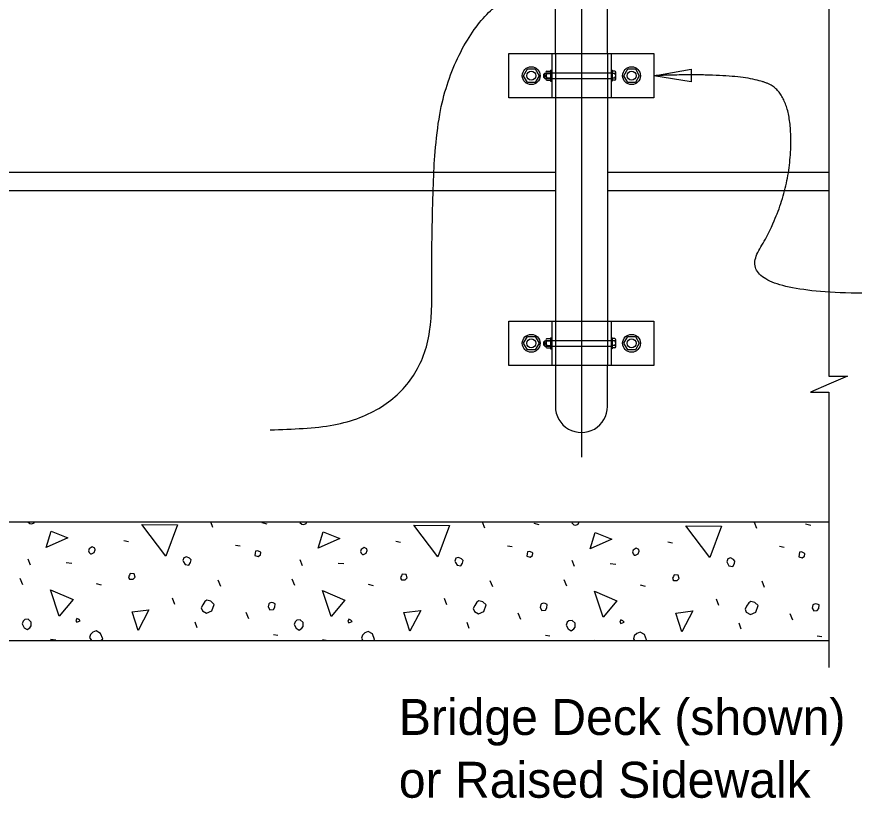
# Model space of a CAD drawing. Extents: x 0 to 41.1, y 0 to 26.4.
# Drawn here: x 19.043 to 23.735, y 12.919 to 17.3 of the extents above; entities that cross this region are included whole.
import ezdxf

# ---------------------------------------------------------------- set-up
doc = ezdxf.new("R2010")
doc.units = 0
for name, color, linetype in [('CL_Major', 7, 'Continuous'), ('Dimension', 7, 'Continuous'), ('Miscellaneous', 7, 'Continuous'), ('SteelMisc', 7, 'Continuous'), ('SteelMisc_h', 7, 'Continuous'), ('SupstrConc', 7, 'Continuous')]:
    doc.layers.add(name, color=color, linetype=linetype)

msp = doc.modelspace()

# ---------------------------------------------------------------- linework, layer by layer
at = {"layer": 'CL_Major'}
msp.add_line((22.2062, 25.6784), (22.2062, 14.8312), dxfattribs=at)
at = {"layer": 'Dimension'}
for points in [[(23.5932, 20.1983), (23.5932, 19.1806), (23.6966, 19.1806), (23.5932, 19.1356), (23.4899, 19.0906), (23.5932, 19.0906), (23.5932, 16.8862)], [(23.5932, 17.1362), (23.5932, 15.2854), (23.6966, 15.2854), (23.5932, 15.2404), (23.4899, 15.1954), (23.5932, 15.1954), (23.5932, 13.6529)]]:
    msp.add_lwpolyline(points, dxfattribs=at)
msp.add_lwpolyline([(22.8207, 16.9356), (22.6122, 16.9694), (22.8202, 17.0062)], close=True, dxfattribs=at)
for points in [[(20.4632, 14.9843), (21.3717, 14.9643), (21.3652, 16.4454), (21.4405, 16.9433), (21.6515, 17.3204), (21.8903, 17.4554), (21.9647, 17.4872), (22.0043, 17.5089), (21.982, 17.3708), (21.7151, 17.4193)], [(23.9932, 15.7529), (23.0399, 15.7236), (23.3618, 16.2556), (23.3935, 16.8155), (23.1813, 16.9916), (22.6122, 16.9694)]]:
    msp.add_open_spline(points, degree=2, dxfattribs=at)
at = {"layer": 'Miscellaneous'}
for p, q in [((21.9986, 16.9625), (21.9986, 16.9746)), ((22.0044, 16.9625), (22.0044, 16.9746)), ((21.9986, 15.4625), (21.9986, 15.4746)), ((22.0044, 15.4625), (22.0044, 15.4746)), ((20.141, 14.4376), (20.1292, 14.4695)), ((20.415, 14.4641), (20.4432, 14.4571)), ((21.6648, 14.4341), (21.6524, 14.4677)), ((21.9388, 14.4606), (21.9671, 14.4535)), ((23.1886, 14.4306), (23.1762, 14.4641)), ((23.4626, 14.4571), (23.4909, 14.45)), ((19.6424, 14.3634), (19.669, 14.3581)), ((21.1663, 14.3599), (21.1928, 14.3545)), ((20.2682, 14.3386), (20.2947, 14.3333)), ((21.792, 14.3351), (21.8186, 14.3298)), ((22.6901, 14.3563), (22.7166, 14.351)), ((23.3159, 14.3316), (23.3424, 14.3263)), ((19.1192, 14.2255), (19.1068, 14.2591)), ((19.3189, 14.2414), (19.3508, 14.2379)), ((20.643, 14.222), (20.6306, 14.2556)), ((20.8428, 14.2379), (20.8746, 14.2343)), ((22.1668, 14.2184), (22.1544, 14.252)), ((22.3666, 14.2343), (22.3984, 14.2308)), ((19.0768, 14.1159), (19.0626, 14.1513)), ((20.1851, 14.1071), (20.171, 14.1424)), ((20.6006, 14.1124), (20.5864, 14.1477)), ((21.709, 14.1035), (21.6948, 14.1389)), ((22.1244, 14.1088), (22.1102, 14.1442)), ((23.2328, 14.1), (23.2186, 14.1353)), ((19.4869, 14.123), (19.5152, 14.1159)), ((21.0107, 14.1194), (21.039, 14.1124)), ((22.5345, 14.1159), (22.5628, 14.1088)), ((19.9288, 14.0063), (19.9147, 14.0417)), ((21.4526, 14.0028), (21.4385, 14.0381)), ((22.9765, 13.9992), (22.9623, 14.0346)), ((20.3425, 13.925), (20.3283, 13.9603)), ((21.8663, 13.9214), (21.8522, 13.9568)), ((23.3901, 13.9179), (23.376, 13.9533)), ((20.0543, 13.8737), (20.042, 13.9073)), ((21.5781, 13.8702), (21.5658, 13.9038)), ((23.102, 13.8666), (23.0896, 13.9002)), ((19.2323, 13.8118), (19.2624, 13.8065)), ((20.4804, 13.8366), (20.5051, 13.8331)), ((20.7561, 13.8083), (20.7862, 13.803)), ((22.0042, 13.8331), (22.0289, 13.8295)), ((22.28, 13.8048), (22.2912, 13.8028)), ((23.528, 13.8295), (23.5527, 13.826))]:
    msp.add_line(p, q, dxfattribs=at)
for points in [[(19.105, 14.4695), (19.1156, 14.4588)], [(19.1156, 14.4588), (19.128, 14.4571), (19.1404, 14.4624), (19.1428, 14.4695)], [(19.8776, 14.2768), (19.7432, 14.4535), (19.943, 14.4518), (19.8776, 14.2768)], [(20.63, 14.4695), (20.6289, 14.4659), (20.6395, 14.4553)], [(20.6395, 14.4553), (20.6518, 14.4535), (20.6642, 14.4588), (20.6677, 14.4695)], [(22.155, 14.4695), (22.1527, 14.4624), (22.1633, 14.4518)], [(22.1633, 14.4518), (22.1757, 14.45), (22.188, 14.4553), (22.1916, 14.4659), (22.1894, 14.4695)], [(19.2076, 14.3245), (19.2359, 14.4164), (19.3295, 14.3793), (19.2076, 14.3245)], [(20.7314, 14.321), (20.7597, 14.4129), (20.8534, 14.3758), (20.7314, 14.321)], [(21.4014, 14.2732), (21.267, 14.45), (21.4668, 14.4482), (21.4014, 14.2732)], [(22.2552, 14.3174), (22.2835, 14.4093), (22.3772, 14.3722), (22.2552, 14.3174)], [(22.9252, 14.2697), (22.7908, 14.4465), (22.9906, 14.4447), (22.9252, 14.2697)], [(19.4551, 14.2891), (19.4621, 14.2891), (19.4763, 14.2962), (19.4816, 14.3121), (19.4798, 14.321), (19.4657, 14.328), (19.448, 14.3174), (19.4445, 14.3068), (19.448, 14.2962), (19.4551, 14.2891)], [(20.9789, 14.2856), (20.9859, 14.2856), (21.0001, 14.2927), (21.0054, 14.3086), (21.0036, 14.3174), (20.9895, 14.3245), (20.9718, 14.3139), (20.9683, 14.3033), (20.9718, 14.2927), (20.9789, 14.2856)], [(22.5027, 14.2821), (22.5098, 14.2821), (22.5239, 14.2891), (22.5292, 14.305), (22.5274, 14.3139), (22.5133, 14.321), (22.4956, 14.3104), (22.4921, 14.2997), (22.4956, 14.2891), (22.5027, 14.2821)], [(19.9766, 14.2449), (19.9854, 14.229), (20.0066, 14.2255), (20.0154, 14.2414), (20.019, 14.2556), (20.0101, 14.2644), (19.9942, 14.2732), (19.9783, 14.2679), (19.973, 14.252), (19.9766, 14.2449)], [(20.3761, 14.2803), (20.3955, 14.275), (20.4079, 14.2838), (20.4097, 14.2962), (20.4061, 14.2997), (20.392, 14.3068), (20.3796, 14.305), (20.3778, 14.2927), (20.3761, 14.2803)], [(21.5004, 14.2414), (21.5092, 14.2255), (21.5304, 14.222), (21.5393, 14.2379), (21.5428, 14.252), (21.534, 14.2609), (21.518, 14.2697), (21.5021, 14.2644), (21.4968, 14.2485), (21.5004, 14.2414)], [(21.8999, 14.2768), (21.9193, 14.2715), (21.9317, 14.2803), (21.9335, 14.2927), (21.9299, 14.2962), (21.9158, 14.3033), (21.9034, 14.3015), (21.9016, 14.2891), (21.8999, 14.2768)], [(23.0242, 14.2379), (23.033, 14.222), (23.0542, 14.2184), (23.0631, 14.2343), (23.0666, 14.2485), (23.0578, 14.2573), (23.0419, 14.2662), (23.0259, 14.2609), (23.0206, 14.2449), (23.0242, 14.2379)], [(23.4237, 14.2732), (23.4431, 14.2679), (23.4555, 14.2768), (23.4573, 14.2891), (23.4537, 14.2927), (23.4396, 14.2997), (23.4272, 14.298), (23.4255, 14.2856), (23.4237, 14.2732)], [(19.6743, 14.1477), (19.6955, 14.1477), (19.7061, 14.1583), (19.7008, 14.1778), (19.6778, 14.1795), (19.6743, 14.1689), (19.669, 14.1601), (19.6743, 14.1477), (19.6707, 14.1513)], [(21.1981, 14.1442), (21.2193, 14.1442), (21.2299, 14.1548), (21.2246, 14.1742), (21.2016, 14.176), (21.1981, 14.1654), (21.1928, 14.1566), (21.1981, 14.1442), (21.1945, 14.1477)], [(22.7219, 14.1406), (22.7431, 14.1406), (22.7537, 14.1513), (22.7484, 14.1707), (22.7254, 14.1725), (22.7219, 14.1619), (22.7166, 14.153), (22.7219, 14.1406), (22.7184, 14.1442)], [(19.2801, 13.9409), (19.2323, 14.0876), (19.3578, 14.0328), (19.2801, 13.9409)], [(20.8039, 13.9374), (20.7561, 14.0841), (20.8816, 14.0293), (20.8039, 13.9374)], [(22.3277, 13.9338), (22.28, 14.0805), (22.4055, 14.0257), (22.3277, 13.9338)], [(20.0826, 13.9692), (20.1056, 13.9568), (20.1356, 13.9692), (20.148, 14.0063), (20.1303, 14.024), (20.1074, 14.0293), (20.0968, 14.0222), (20.0844, 14.0028), (20.0755, 13.9869), (20.0826, 13.9692)], [(20.4521, 13.9922), (20.4609, 13.9762), (20.4804, 13.978), (20.4892, 13.9904), (20.491, 14.0098), (20.4786, 14.0151), (20.4698, 14.0169), (20.4592, 14.0134), (20.4556, 14.0098), (20.4521, 13.9922)], [(21.6064, 13.9656), (21.6294, 13.9533), (21.6595, 13.9656), (21.6718, 14.0028), (21.6542, 14.0204), (21.6312, 14.0257), (21.6206, 14.0187), (21.6082, 13.9992), (21.5994, 13.9833), (21.6064, 13.9656)], [(21.9759, 13.9886), (21.9847, 13.9727), (22.0042, 13.9745), (22.013, 13.9869), (22.0148, 14.0063), (22.0024, 14.0116), (21.9936, 14.0134), (21.983, 14.0098), (21.9794, 14.0063), (21.9759, 13.9886)], [(23.1302, 13.9621), (23.1532, 13.9497), (23.1833, 13.9621), (23.1957, 13.9992), (23.178, 14.0169), (23.155, 14.0222), (23.1444, 14.0151), (23.132, 13.9957), (23.1232, 13.9798), (23.1302, 13.9621)], [(23.4997, 13.9851), (23.5085, 13.9692), (23.528, 13.9709), (23.5368, 13.9833), (23.5386, 14.0028), (23.5262, 14.0081), (23.5174, 14.0098), (23.5068, 14.0063), (23.5032, 14.0028), (23.4997, 13.9851)], [(19.722, 13.8596), (19.6884, 13.9639), (19.7821, 13.9762), (19.722, 13.8596)], [(21.2458, 13.856), (21.2122, 13.9603), (21.3059, 13.9727), (21.2458, 13.856)], [(22.7696, 13.8525), (22.736, 13.9568), (22.8297, 13.9692), (22.7696, 13.8525)], [(19.0732, 13.8967), (19.0838, 13.8755), (19.1015, 13.8649), (19.1156, 13.8755), (19.1227, 13.8861), (19.1227, 13.9073), (19.1068, 13.9232), (19.0874, 13.9214), (19.0785, 13.9126), (19.0732, 13.8967)], [(19.379, 13.9055), (19.3985, 13.9144), (19.3914, 13.9214), (19.379, 13.9267), (19.3737, 13.9144), (19.379, 13.9055)], [(20.597, 13.8932), (20.6076, 13.8719), (20.6253, 13.8613), (20.6395, 13.8719), (20.6465, 13.8826), (20.6465, 13.9038), (20.6306, 13.9197), (20.6112, 13.9179), (20.6023, 13.9091), (20.597, 13.8932)], [(20.9029, 13.902), (20.9223, 13.9108), (20.9152, 13.9179), (20.9029, 13.9232), (20.8976, 13.9108), (20.9029, 13.902)], [(22.1209, 13.8896), (22.1315, 13.8684), (22.1491, 13.8578), (22.1633, 13.8684), (22.1703, 13.879), (22.1703, 13.9002), (22.1544, 13.9161), (22.135, 13.9144), (22.1262, 13.9055), (22.1209, 13.8896)], [(22.4267, 13.8985), (22.4461, 13.9073), (22.4391, 13.9144), (22.4267, 13.9197), (22.4214, 13.9073), (22.4267, 13.8985)], [(19.5132, 13.8028), (19.524, 13.8136), (19.5116, 13.8437), (19.4869, 13.8578), (19.4692, 13.8507), (19.4551, 13.8366), (19.4498, 13.8207)], [(21.0405, 13.8028), (21.0478, 13.8101), (21.0354, 13.8401), (21.0107, 13.8543), (20.993, 13.8472), (20.9789, 13.8331), (20.9736, 13.8171)], [(22.5679, 13.8028), (22.5716, 13.8065), (22.5593, 13.8366), (22.5345, 13.8507), (22.5168, 13.8437), (22.5027, 13.8295), (22.4974, 13.8136)], [(19.4498, 13.8207), (19.4608, 13.8028)], [(20.9736, 13.8171), (20.9825, 13.8028)], [(22.4974, 13.8136), (22.5041, 13.8028)]]:
    msp.add_lwpolyline(points, dxfattribs=at)
at = {"layer": 'SteelMisc'}
for p, q in [((22.0604, 17.0944), (22.0604, 17.7968)), ((22.3521, 17.0944), (22.3521, 17.7968)), ((21.8002, 17.0944), (22.6122, 17.0944)), ((21.8002, 16.8444), (21.8002, 17.0944)), ((22.0396, 17.0944), (22.0396, 16.8444)), ((22.3729, 17.0944), (22.3729, 16.8444)), ((22.6122, 17.0944), (22.6122, 16.8444)), ((22.008, 16.9873), (22.008, 16.9516)), ((22.0129, 16.9954), (22.033, 16.9954)), ((22.033, 16.9997), (22.033, 16.9391)), ((22.033, 16.9997), (22.0396, 16.9997)), ((22.033, 16.9954), (22.033, 16.9435)), ((22.3792, 16.9997), (22.3731, 16.9997)), ((22.3939, 16.9954), (22.3791, 16.9954)), ((22.3792, 16.9997), (22.3792, 16.9391)), ((22.399, 16.95), (22.399, 16.9889)), ((21.9958, 16.9774), (22.0015, 16.984)), ((21.9958, 16.9597), (21.9958, 16.9774)), ((21.9958, 16.9597), (22.0015, 16.9541)), ((22.0015, 16.984), (22.008, 16.984)), ((22.0015, 16.9541), (22.0015, 16.984)), ((22.0015, 16.9541), (22.008, 16.9541)), ((22.0127, 16.9824), (22.033, 16.9824)), ((22.0127, 16.9565), (22.033, 16.9565)), ((22.013, 16.9435), (22.033, 16.9435)), ((22.033, 16.9391), (22.0396, 16.9391)), ((22.3792, 16.9391), (22.3731, 16.9391)), ((22.394, 16.9824), (22.3791, 16.9824)), ((22.394, 16.9564), (22.3791, 16.9564)), ((22.3939, 16.9434), (22.3791, 16.9434)), ((22.6122, 16.8444), (21.8002, 16.8444)), ((22.0604, 16.8444), (22.0604, 15.5944)), ((22.3521, 16.8444), (22.3521, 15.5944)), ((21.8002, 15.5944), (22.6122, 15.5944)), ((21.8002, 15.3444), (21.8002, 15.5944)), ((22.0396, 15.5944), (22.0396, 15.3444)), ((22.3729, 15.5944), (22.3729, 15.3444)), ((22.6122, 15.5944), (22.6122, 15.3444)), ((22.008, 15.4873), (22.008, 15.4516)), ((22.0129, 15.4954), (22.033, 15.4954)), ((22.033, 15.4997), (22.033, 15.4391)), ((22.033, 15.4997), (22.0396, 15.4997)), ((22.033, 15.4954), (22.033, 15.4435)), ((22.3792, 15.4997), (22.3731, 15.4997)), ((22.3939, 15.4954), (22.3791, 15.4954)), ((22.3792, 15.4997), (22.3792, 15.4391)), ((22.399, 15.45), (22.399, 15.4889)), ((21.9958, 15.4774), (22.0015, 15.484)), ((21.9958, 15.4597), (21.9958, 15.4774)), ((21.9958, 15.4597), (22.0015, 15.4541)), ((22.0015, 15.484), (22.008, 15.484)), ((22.0015, 15.4541), (22.0015, 15.484)), ((22.0015, 15.4541), (22.008, 15.4541)), ((22.0127, 15.4824), (22.033, 15.4824)), ((22.0127, 15.4565), (22.033, 15.4565)), ((22.013, 15.4435), (22.033, 15.4435)), ((22.033, 15.4391), (22.0396, 15.4391)), ((22.3792, 15.4391), (22.3731, 15.4391)), ((22.394, 15.4824), (22.3791, 15.4824)), ((22.394, 15.4564), (22.3791, 15.4564)), ((22.3939, 15.4434), (22.3791, 15.4434)), ((22.6122, 15.3444), (21.8002, 15.3444)), ((22.0603, 15.3444), (22.0603, 15.1153)), ((22.3519, 15.1153), (22.3519, 15.3444))]:
    msp.add_line(p, q, dxfattribs=at)
for points in [[(21.9036, 17.007), (21.9469, 17.007), (21.9686, 16.9694), (21.9469, 16.9319), (21.9036, 16.9319), (21.8819, 16.9694)], [(22.4655, 17.007), (22.5089, 17.007), (22.5305, 16.9694), (22.5089, 16.9319), (22.4655, 16.9319), (22.4439, 16.9694)], [(21.9036, 15.507), (21.9469, 15.507), (21.9686, 15.4694), (21.9469, 15.4319), (21.9036, 15.4319), (21.8819, 15.4694)], [(22.4655, 15.507), (22.5089, 15.507), (22.5305, 15.4694), (22.5089, 15.4319), (22.4655, 15.4319), (22.4439, 15.4694)]]:
    msp.add_lwpolyline(points, close=True, dxfattribs=at)
for centre, radius in [((21.9252, 16.9694), 0.05), ((21.9252, 16.9694), 0.025), ((22.4872, 16.9694), 0.05), ((22.4872, 16.9694), 0.025), ((21.9252, 15.4694), 0.05), ((21.9252, 15.4694), 0.025), ((22.4872, 15.4694), 0.05), ((22.4872, 15.4694), 0.025)]:
    msp.add_circle(centre, radius, dxfattribs=at)
for centre, radius, start, end in [((22.0145, 16.9889), 0.00674, 104.4891, 254.1889), ((22.3922, 16.9889), 0.00673, 285.7823, 75.5404), ((22.0274, 16.9694), 0.0196, 138.628, 221.372), ((22.0145, 16.95), 0.00673, 105.7823, 255.5404), ((22.3922, 16.95), 0.00674, 284.4891, 74.1889), ((22.3793, 16.9694), 0.0196, 318.628, 41.372), ((22.0145, 15.4889), 0.00674, 104.4891, 254.1889), ((22.3922, 15.4889), 0.00673, 285.7823, 75.5404), ((22.0274, 15.4694), 0.0196, 138.628, 221.372), ((22.0145, 15.45), 0.00673, 105.7823, 255.5404), ((22.3922, 15.45), 0.00674, 284.4891, 74.1889), ((22.3793, 15.4694), 0.0196, 318.628, 41.372)]:
    msp.add_arc(centre, radius, start, end, dxfattribs=at)
msp.add_ellipse((22.2062, 15.1153), major_axis=(0, 0.1458), ratio=0.999499, start_param=1.570796, end_param=4.712389, dxfattribs=at)
at = {"layer": 'SteelMisc_h'}
for p, q in [((22.0604, 17.0944), (22.0604, 16.8444)), ((22.3521, 17.0944), (22.3521, 16.8444)), ((22.3729, 16.984), (22.008, 16.984)), ((22.008, 16.9541), (22.3729, 16.9541)), ((22.0604, 15.5944), (22.0604, 15.3444)), ((22.3521, 15.5944), (22.3521, 15.3444)), ((22.3729, 15.484), (22.008, 15.484)), ((22.008, 15.4541), (22.3729, 15.4541))]:
    msp.add_line(p, q, dxfattribs=at)
at = {"layer": 'SupstrConc'}
for p, q in [((12.3521, 16.4295), (22.0604, 16.4295)), ((22.3521, 16.4295), (23.5931, 16.4295)), ((12.3521, 16.3254), (22.0604, 16.3254)), ((22.3521, 16.3254), (23.5931, 16.3254)), ((0.8193, 14.4695), (23.5931, 14.4695)), ((0.8193, 13.8028), (23.5931, 13.8028))]:
    msp.add_line(p, q, dxfattribs=at)

# ---------------------------------------------------------------- texts
at = {"layer": 'Dimension'}
for s, p in [('Bridge Deck (shown)', (21.1833, 13.2743)), ('or Raised Sidewalk', (21.1833, 12.9223))]:
    msp.add_text(s, height=0.2016, dxfattribs=at).set_placement(p)

doc.saveas('drawing.dxf')
